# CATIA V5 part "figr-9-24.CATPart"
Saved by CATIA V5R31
Part number: Part2
Bounding box of the stored display mesh (mm): x -72 to 72, y -80 to 90, z -20 to 41.296
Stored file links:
  D:\PROJECTS\Project 2021\US EDITION\CATIA V5 6R 2021\Resources\Part Files\c09_catia_v5_6r2021_prt\c09_catia_v5_6r2021_prt\figr-9-24.CATPart
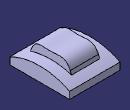
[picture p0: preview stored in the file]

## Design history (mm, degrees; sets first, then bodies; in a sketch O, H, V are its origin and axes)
Body1 (main body)
  Sketch1 on yz-plane, origin (0, 0, 0), H (0, 1, 0), V (0, 0, 1)
    arc A1 centre (5, -170) radius 190.0658 from (-80, 0) to (90, 0) cw
    point P2 (-80, 0)
    point P3 (0, 20)
    line L1 (-80, 0) -> (-80, -20)
    line L2 (-80, -20) -> (90, -20)
    line L3 (90, -20) -> (90, 0)
    coincidence: P2 H, A1 P3, P3 V
    vertical: L1 V, L3 V
    horizontal: L2 H
  Pad1: profile Sketch1, direction (1, 0, 0), length 72, mirrored extent
  Sketch2 on yz-plane, origin (0, 0, 0), H (0, 1, 0), V (0, 0, 1)
    spline S1 through (60, 20) (40, 40) (10, 40) (-10, 40) (-30, 40) (-50, 20)
  Sketch3 on zx-plane, origin (0, 0, 0), H (-1, 0, 0), V (0, 0, 1)
    line L1 (-40, 30) -> (40, 30)
    horizontal: L1 H
  Rib1: profile Sketch2, centre curve Sketch3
